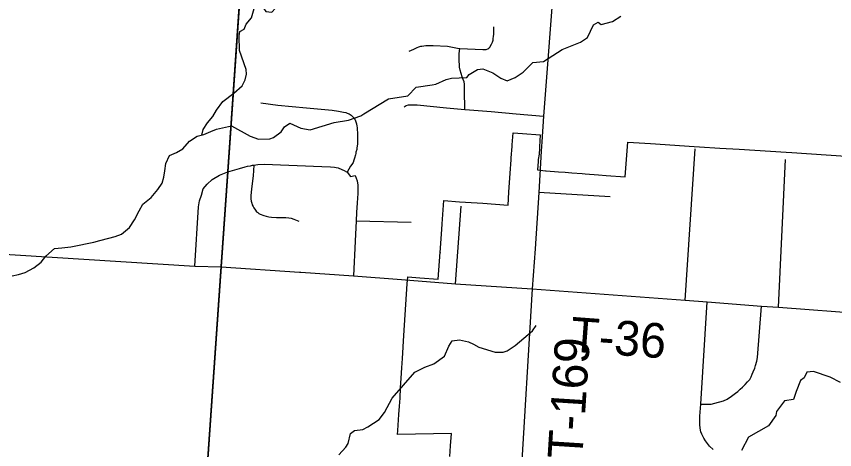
# Model space of a CAD drawing. Extents: x 0 to 34, y 0 to 22.
# Drawn here: x 3.515 to 4.853, y 18.458 to 19.167 of the extents above; entities that cross this region are included whole.
import ezdxf

# ---------------------------------------------------------------- set-up
doc = ezdxf.new("R2010")
doc.units = 0
for name, color, linetype in [('GM_X_City_Street', 7, 'Continuous'), ('GM_X_Corporation', 7, 'Continuous'), ('GM_X_County', 7, 'Continuous'), ('GM_X_Minor_River', 7, 'Continuous'), ('GM_X_Township_Road', 7, 'Continuous'), ('GM_X_Township_Road_Text', 7, 'Continuous')]:
    doc.layers.add(name, color=color, linetype=linetype)

msp = doc.modelspace()

# ---------------------------------------------------------------- linework, layer by layer
at = {"layer": 'GM_X_City_Street'}
msp.add_line((4.0709, 18.8319), (4.1609, 18.8302), dxfattribs=at)
for points in [[(4.1576, 19.1099), (4.1652, 19.1133), (4.1705, 19.1159), (4.1731, 19.1167), (4.1765, 19.1178), (4.178, 19.1178), (4.1815, 19.1185), (4.1849, 19.1193), (4.1902, 19.1193), (4.197, 19.1192), (4.22, 19.118), (4.2393, 19.1141), (4.2404, 19.1141), (4.2779, 19.1124), (4.2809, 19.1124), (4.2836, 19.1128), (4.2859, 19.1135), (4.2878, 19.115), (4.2893, 19.1165), (4.292, 19.1215), (4.2935, 19.1245), (4.2946, 19.1279), (4.295, 19.1302), (4.2954, 19.1344), (4.2958, 19.1374), (4.2958, 19.1412), (4.2959, 19.1495)], [(4.2484, 19.0142), (4.2483, 19.0222), (4.248, 19.0381), (4.2481, 19.051), (4.2481, 19.0556), (4.2474, 19.0594), (4.2459, 19.0636), (4.2444, 19.0677), (4.2407, 19.0788), (4.2399, 19.0837), (4.2396, 19.0879), (4.2392, 19.0928), (4.2392, 19.0966), (4.2393, 19.0993), (4.2393, 19.1061), (4.2404, 19.1141)], [(3.915, 19.0252), (3.943, 19.0217), (3.9899, 19.0173), (4.0315, 19.0133), (4.0421, 19.0117), (4.0504, 19.0101), (4.0542, 19.0094), (4.0564, 19.0086), (4.0595, 19.0074), (4.0625, 19.0052), (4.0655, 19.0025), (4.0674, 19.0002), (4.0689, 18.9983), (4.07, 18.996), (4.0704, 18.9941), (4.0715, 18.9907), (4.0722, 18.9873), (4.0726, 18.985), (4.0726, 18.9823), (4.0733, 18.9759), (4.0728, 18.9576), (4.0721, 18.9519), (4.0717, 18.9489), (4.0705, 18.9444), (4.0701, 18.9425), (4.0697, 18.9402), (4.0682, 18.9345), (4.067, 18.9315), (4.0659, 18.9277), (4.064, 18.9246), (4.0617, 18.9216), (4.0559, 18.9117)], [(4.1492, 19.0188), (4.1526, 19.0207), (4.1564, 19.0218), (4.1587, 19.0222), (4.1625, 19.0222), (4.1708, 19.0218), (4.2184, 19.017), (4.2484, 19.0142), (4.2491, 19.0142), (4.2918, 19.0109), (4.3323, 19.0073), (4.3773, 19.0035)], [(3.8611, 18.9124), (3.8804, 18.9179), (3.8895, 18.9205), (3.8933, 18.9216), (3.8979, 18.9224), (3.9013, 18.9231), (3.9036, 18.9234), (3.9104, 18.9242), (3.9206, 18.9249), (4.0148, 18.9211), (4.0288, 18.9206), (4.0352, 18.9198), (4.0382, 18.9194), (4.0412, 18.9187), (4.0477, 18.9163), (4.0511, 18.9148), (4.0552, 18.9125), (4.0559, 18.9117), (4.0616, 18.9049), (4.0693, 18.9063), (4.0726, 18.8974), (4.0737, 18.8903), (4.0735, 18.8771), (4.0723, 18.8617), (4.0715, 18.846), (4.0709, 18.8319), (4.0692, 18.7986), (4.0666, 18.742)], [(3.9036, 18.9234), (3.9027, 18.906), (3.8999, 18.8844), (3.8988, 18.873), (3.8987, 18.868), (3.8991, 18.8646), (3.9002, 18.8608), (3.901, 18.8582), (3.9025, 18.8555), (3.9036, 18.8532), (3.9062, 18.8498), (3.9081, 18.8471), (3.91, 18.8456), (3.9119, 18.8444), (3.9138, 18.8433), (3.9202, 18.841), (3.924, 18.8398), (3.9281, 18.8387), (3.9323, 18.8379), (3.9406, 18.8375), (3.9482, 18.8374), (3.9557, 18.8374), (3.961, 18.837), (3.9648, 18.8366), (3.969, 18.8351), (3.9769, 18.8316)], [(3.8074, 18.7581), (3.8134, 18.8552), (3.815, 18.865), (3.8178, 18.874), (3.8206, 18.8843), (3.8272, 18.8921), (3.8353, 18.8996), (3.8475, 18.9069), (3.8611, 18.9124)], [(3.1008, 18.8442), (3.1851, 18.8373), (3.3272, 18.8289), (3.3394, 18.8284), (3.35, 18.8265), (3.3622, 18.8213), (3.4317, 18.7858), (3.4398, 18.7825), (3.4526, 18.7804), (3.8074, 18.7581), (3.8503, 18.7566)]]:
    msp.add_lwpolyline(points, dxfattribs=at)
at = {"layer": 'GM_X_Corporation'}
msp.add_lwpolyline([(4.3071, 20.9), (2.1, 20.9), (2.1, 14.1), (3.0169, 14.1), (3.0406, 14.4484), (3.1026, 15.287), (3.1745, 16.2606), (2.934, 16.2765), (2.366, 16.3159), (2.2862, 16.3208), (2.1768, 16.323), (2.2478, 17.3472), (2.3155, 18.3567), (3.8153, 18.2543), (3.8503, 18.7566), (3.8611, 18.9124), (3.8924, 19.3621), (3.9019, 19.4987), (3.9133, 19.6628), (3.9816, 20.645), (3.9912, 20.7822), (4.2975, 20.7549)], close=True, dxfattribs=at)
for points in [[(3.8151, 18.2549), (3.8501, 18.7572), (3.8609, 18.9129), (3.8918, 19.3576), (3.8924, 19.3656), (3.9015, 19.4967), (3.9015, 19.497), (3.9131, 19.6633), (3.9131, 19.6638), (3.9335, 19.9563), (3.9417, 20.0742), (3.9814, 20.6455), (3.9909, 20.7828), (4.2973, 20.7554), (4.3068, 20.9), (2.1, 20.9), (2.1, 14.1)], [(3.8151, 18.2549), (3.8501, 18.7572), (3.8609, 18.9129), (3.8918, 19.3576), (3.8924, 19.3656), (3.9015, 19.4967), (3.9015, 19.497), (3.9131, 19.6633), (3.9131, 19.6638), (3.9335, 19.9563), (3.9417, 20.0742), (3.9814, 20.6455), (3.9909, 20.7828), (3.2798, 20.8248), (2.7336, 20.8606), (2.2596, 20.8916), (2.1, 20.8993), (2.1, 16.3272)], [(8.9, 20.9), (4.3068, 20.9), (4.2973, 20.7554), (3.9909, 20.7828), (3.9814, 20.6455), (3.9417, 20.0742), (3.9335, 19.9563), (3.9131, 19.6638), (3.9131, 19.6633), (3.9015, 19.497), (3.9015, 19.4967), (3.8924, 19.3656), (3.8918, 19.3576), (3.8609, 18.9129), (3.8501, 18.7572), (3.8151, 18.2549)], [(8.9, 20.9), (4.3071, 20.9), (4.2975, 20.7549), (3.9912, 20.7822), (3.9816, 20.645), (3.9133, 19.6628), (3.9019, 19.4987), (3.8924, 19.3621), (3.8611, 18.9124), (3.8503, 18.7566), (3.8153, 18.2543), (4.1999, 18.2271), (4.3271, 18.2226), (4.5528, 18.2021), (4.7449, 18.1929), (4.9551, 18.1768), (5.5447, 18.1318), (5.8371, 18.1158), (5.9465, 18.1082), (6.0343, 18.1015), (6.0906, 18.0978), (6.5646, 18.0583)], [(6.676, 20.6183), (5.8237, 20.6711), (5.4957, 20.69), (5.3653, 20.6955), (5.2473, 20.7005), (5.2396, 20.7003), (4.8574, 20.7216), (4.6201, 20.7441), (4.5367, 20.7456), (4.2973, 20.7554), (3.9909, 20.7828), (3.9814, 20.6455), (3.9417, 20.0742), (3.9335, 19.9563), (3.9131, 19.6638), (3.9131, 19.6633), (3.9015, 19.497), (3.9015, 19.4967), (3.8924, 19.3656), (3.8918, 19.3576), (3.8609, 18.9129), (3.8501, 18.7572), (3.8151, 18.2549)], [(4.224, 18.4463), (4.2252, 18.464), (4.2265, 18.4838), (4.1386, 18.4824), (4.1391, 18.4889), (4.1408, 18.515), (4.1418, 18.5286), (4.1427, 18.5418), (4.1434, 18.5588), (4.1444, 18.5748), (4.1455, 18.5918), (4.1464, 18.6068), (4.1488, 18.6442), (4.1543, 18.7291), (4.1554, 18.7404), (4.1747, 18.739), (4.2048, 18.7369), (4.208, 18.7806), (4.2083, 18.7805), (4.2111, 18.8182), (4.2117, 18.8275), (4.214, 18.8655), (4.2399, 18.8635), (4.2494, 18.8627), (4.2778, 18.8608), (4.2986, 18.8593), (4.3191, 18.8579), (4.3206, 18.8791), (4.3227, 18.9103), (4.3243, 18.9321), (4.3245, 18.9352), (4.3259, 18.9537), (4.3261, 18.9567), (4.3275, 18.9761), (4.3429, 18.975), (4.3718, 18.9729), (4.3706, 18.9535), (4.3704, 18.9506), (4.3698, 18.9411), (4.3686, 18.9326), (4.3684, 18.9295), (4.3673, 18.9154), (4.3802, 18.9142), (4.3813, 18.9141), (4.4016, 18.9125), (4.4127, 18.9117), (4.4236, 18.9108), (4.4401, 18.9095), (4.4453, 18.9091), (4.467, 18.9074), (4.4796, 18.9064), (4.5104, 18.9041), (4.5121, 18.9253), (4.5149, 18.9607), (4.5523, 18.9585), (4.6232, 18.954), (4.632, 18.9534), (4.6654, 18.9513), (4.6969, 18.9493), (4.7739, 18.9444), (4.7833, 18.9438), (4.8712, 18.9382)]]:
    msp.add_lwpolyline(points, dxfattribs=at)
at = {"layer": 'GM_X_County'}
msp.add_lwpolyline([(3.8151, 18.2549), (3.8501, 18.7572), (3.8609, 18.9129), (3.8918, 19.3576), (3.8924, 19.3656), (3.9015, 19.4967), (3.9015, 19.497), (3.9131, 19.6633), (3.9131, 19.6638), (3.9335, 19.9563), (3.9417, 20.0742), (3.9814, 20.6455), (3.9909, 20.7828), (4.2973, 20.7554), (4.3068, 20.9)], dxfattribs=at)
at = {"layer": 'GM_X_Minor_River'}
for points in [[(3.8708, 19.0413), (3.8843, 19.053), (3.8896, 19.0629), (3.8915, 19.0724), (3.8908, 19.0796), (3.8802, 19.1107), (3.8795, 19.135), (3.8806, 19.1418), (3.8878, 19.146), (3.8912, 19.154), (3.8999, 19.1642), (3.9053, 19.1835), (3.9117, 19.1866), (3.9193, 19.1805), (3.9234, 19.1748), (3.9329, 19.1736), (3.9389, 19.1801), (3.9537, 19.2074), (3.9507, 19.2226), (3.956, 19.2233), (3.9621, 19.226), (3.975, 19.2578)], [(3.867, 18.9877), (3.8978, 18.971), (3.911, 18.9661), (3.93, 18.9664), (3.936, 18.9683), (3.9485, 18.9778), (3.9538, 18.9861), (3.9622, 18.9922), (3.9807, 18.9838), (3.9958, 18.9811), (4.0348, 18.9932), (4.0586, 18.997), (4.0787, 19.0038), (4.0836, 19.0072), (4.1238, 19.0319), (4.1552, 19.0368), (4.1688, 19.0508), (4.1953, 19.0545), (4.201, 19.0557), (4.218, 19.0636), (4.2267, 19.0659), (4.2517, 19.0666), (4.2555, 19.0719), (4.2691, 19.0799), (4.2782, 19.081), (4.2941, 19.0745), (4.3073, 19.0658), (4.3175, 19.0612), (4.3307, 19.0665), (4.344, 19.0756), (4.3599, 19.0912), (4.3769, 19.093), (4.4076, 19.1124), (4.4375, 19.1245), (4.4489, 19.1324), (4.4587, 19.1529), (4.4663, 19.1571), (4.4712, 19.1536), (4.4898, 19.1582), (4.5038, 19.1669)], [(3.8184, 18.9724), (3.8208, 18.9816), (3.828, 18.9925), (3.8364, 19.0027), (3.8425, 19.0133), (3.8528, 19.0273), (3.8708, 19.0413)], [(3.5084, 18.7424), (3.519, 18.7443), (3.53, 18.7476), (3.5437, 18.7551), (3.5558, 18.7645), (3.5635, 18.7744), (3.5775, 18.7868), (3.59, 18.7879), (3.6044, 18.7897), (3.618, 18.7923), (3.6309, 18.7948), (3.6423, 18.7974), (3.6517, 18.8), (3.6665, 18.8037), (3.6771, 18.8063), (3.6874, 18.8104), (3.7003, 18.8214), (3.7083, 18.8338), (3.716, 18.8486), (3.7224, 18.8596), (3.7358, 18.8705), (3.7468, 18.8833), (3.754, 18.8939), (3.7564, 18.9038), (3.758, 18.914), (3.7595, 18.9261), (3.766, 18.939), (3.777, 18.9439), (3.7873, 18.9499), (3.7983, 18.9627), (3.8112, 18.9706), (3.8218, 18.9732), (3.8332, 18.9784), (3.8427, 18.9822), (3.867, 18.9877)], [(4.0424, 18.449), (4.0538, 18.4615), (4.0576, 18.4679), (4.0618, 18.4838), (4.0682, 18.4892), (4.0818, 18.4907), (4.0898, 18.4952), (4.1083, 18.5069), (4.1174, 18.5187), (4.1299, 18.5418), (4.1667, 18.5843), (4.183, 18.5926), (4.1981, 18.5983), (4.2155, 18.6108), (4.2224, 18.6271), (4.2277, 18.6355), (4.2398, 18.6374), (4.2545, 18.6343), (4.2628, 18.6301), (4.2712, 18.6256), (4.298, 18.6172), (4.3112, 18.6172), (4.3177, 18.6194), (4.3309, 18.6281), (4.359, 18.652), (4.3654, 18.6611)], [(4.8628, 18.5675), (4.8458, 18.5763), (4.8185, 18.5858), (4.8076, 18.5847), (4.8034, 18.5752), (4.797, 18.5707), (4.7901, 18.5528), (4.7859, 18.5399), (4.7712, 18.5373), (4.7579, 18.5202), (4.7568, 18.5134), (4.7447, 18.4967), (4.7125, 18.4781), (4.7007, 18.4561)]]:
    msp.add_lwpolyline(points, dxfattribs=at)
at = {"layer": 'GM_X_Township_Road'}
for p, q in [((4.3733, 18.946), (4.371, 18.9075)), ((4.6089, 18.7022), (4.625, 18.95)), ((4.7612, 18.6909), (4.7726, 18.9328)), ((4.4862, 18.8713), (4.3693, 18.8786)), ((4.2332, 18.7292), (4.2424, 18.856)), ((3.8503, 18.7566), (3.9783, 18.7483))]:
    msp.add_line(p, q, dxfattribs=at)
for points in [[(4.4041, 19.3676), (4.3959, 19.2455), (4.3773, 19.0035), (4.3743, 18.9615), (4.3733, 18.946)], [(4.371, 18.9075), (4.3693, 18.8786), (4.3633, 18.7864), (4.3588, 18.7211)], [(3.9783, 18.7483), (3.9802, 18.7482), (4.0666, 18.742), (4.145, 18.736)], [(4.145, 18.736), (4.2332, 18.7292), (4.3588, 18.7211)], [(4.3588, 18.7211), (4.3393, 18.4034), (4.339, 18.3994)], [(4.3588, 18.7211), (4.6089, 18.7022), (4.6446, 18.6995), (4.7336, 18.6925), (4.7612, 18.6909), (4.9046, 18.6801), (5.1086, 18.6685), (5.1411, 18.6657), (5.1701, 18.6632), (5.1983, 18.6624), (5.4964, 18.642), (6.1506, 18.5908), (6.3173, 18.5789), (6.5773, 18.5635)], [(4.6545, 18.4581), (4.6485, 18.4635), (4.6418, 18.4723), (4.6392, 18.4762), (4.6359, 18.483), (4.6345, 18.4869), (4.6334, 18.493), (4.6327, 18.499), (4.6325, 18.5123), (4.6343, 18.532), (4.6446, 18.6995)], [(4.6343, 18.532), (4.6513, 18.5322), (4.6574, 18.5337), (4.6714, 18.5376), (4.6775, 18.5402), (4.6844, 18.5451), (4.6909, 18.5499), (4.6947, 18.5529), (4.6985, 18.5567), (4.7024, 18.56), (4.7066, 18.5641), (4.7104, 18.5687), (4.7146, 18.5724), (4.7166, 18.5766), (4.7185, 18.5811), (4.7201, 18.5852), (4.7224, 18.5909), (4.7236, 18.5954), (4.7256, 18.6026), (4.7268, 18.6087), (4.7336, 18.6925)]]:
    msp.add_lwpolyline(points, dxfattribs=at)

# ---------------------------------------------------------------- texts
at = {"layer": 'GM_X_Township_Road_Text'}
for s, rotation, p in [('T-36', 355.7645, (4.4197, 18.6183)), ('T-169', 86.3536, (4.4404, 18.4412))]:
    msp.add_text(s, height=0.05682, rotation=rotation, dxfattribs=at).set_placement(p)

doc.saveas('drawing.dxf')
